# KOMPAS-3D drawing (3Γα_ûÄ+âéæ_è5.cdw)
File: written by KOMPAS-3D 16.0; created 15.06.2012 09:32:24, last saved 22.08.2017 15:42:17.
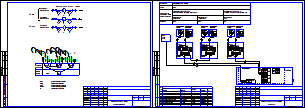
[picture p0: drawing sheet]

Sheets 1-2: A3, landscape

Title block, sheet 1: name: г. Москва, ул. Нежинская, д. 14, к.8 (кв. 1 и кв. 2); sheet number: 1; sheets: 27 / 28; sheet format: A3; stored path: D:\Проекты\Лыткарино\ул. Квартал 3А, д.25\710.74 РП.cdw; cell 320: Р
Title block, sheet 2: sheet number: 2

Views: Вид 2, Вид 3, Вид 4, Вид 5
Referenced files in C:\Program Files (x86)\ASCON\KOMPAS-3D V16\Sys\: SPDS.lcs, EngSys.lcs, GRAPHIC.LHS
Referenced files: graphic.tdp
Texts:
  МО, Клинский район, д. Решетниково, ул. Центральная, д.14
  GOST Common
  Normal
  List Paragraph
  heading 3
  для схемы
  txt
  краны
  Фоновая заливка
  Т0-элементы
  ВРУ
  Плата подключений
  СБ МКТС
  каб.
  Начало
  трассы
  Трассы
  Марка
  Проложен
  Датчик температуры (Т1)
  Датчик температуры (Т2)
  Датчик температуры (Т3)
  Датчик давления (Т1)
  Датчик давления (Т3)
  Датчик давления (Т2)
  Изм. модуль (Т1)
  Изм. модуль (Т2)
  ВРУ 220В, 50 Гц
  Изм. модуль (Т3)
  ИМ1 УУТЭ
  ИМ2 УУТЭ
  ИМ1 УУГВС
  ИМ2 УУГВС
  ИМ (Т1)
  FTP
  ПВС
  Конец
  Кол-во и
  сеч. жил
  Длина,
  Преобразователь расхода
  Термопреобразователь
  Преобразователь давления
  Преобразователь цифровой
  Системный блок МКТС
  приборы
  по месту
  шкаф
  учета
  UQIES
  Подающий
  трубопровод
  Обратный
  УУГВС
  УУТЭ
  Функциональная схема
  Агрегат
  Системный блок  МКТС
  Среда
  Вода
  параметра и место
  отбора импульса
  Учет тепловой энергии и
  теплоносителя системы отопления
  отопления
  расхода горячей воды системы ГВС
  ГВС
  ИМ1
  ИМ2
  ИМ3
  Pt 100
  Преобразователь
  температуры
  давления
  UP+
  UP-
  ИМП
  Лин
  Измерительный
  модуль М121
  Размеры, параметризация
  сит. план
  подача ГВС
  обратка ГВС
  хвс
  обратка
  POLYLINE_STYLE_0.25_RGB_0_0_0
  стены
  Основная (не является границей для штриховки)
  POLYLINE_STYLE_0.18_RGB_0_0_0
  ХВС
  зеленая
  Красная тонкая
  арматура
  Подача
  Скрытая линия
  Ось Z
  Ось Y
  Ось X
  Образующая трубопровода (проектируемого)
  Трубопровод толщиной 0.6мм (одна линия)
  Трубопровод толщиной 1.2мм (одна линия)
  Трубопровод толщиной 1.0мм (одна линия)
  Трубопровод толщиной 0.8мм (одна линия)
  Трубопровод существующий (одна линия)
  Трубопровод невидимый (одна линия)
  Трубопровод демонтируемый (одна линия)
  Осевая трубопровода
  Осевая трубопровода (демонтируемого)
  Образующая трубопровода (существующего)
  Образующая трубопровода (невидимого)
  Изолированный трубопровод проектируемый (одна линия)
  Изолированный трубопровод существующий (одна линия)
  Образующая изоляции
  Изоляция
  Изолированный трубопровод невидимый (одна линия)
  Штрих пвс 075
  штрих пвс 2,5
  существующее оборудование
  Существующее оборудование
  K5LT_BASIC_RGB_0_0_255_THICK_0.53
  POLYLINE_STYLE_1.51_RGB_0_0_255
  POLYLINE_STYLE_0.50_RGB_128_128_128
  K5LT_AXLED_RGB_255_128_0_SC_1_THICK_0.18
  ACAD_ISO04W100_RGB_0_0_0_SC_1_THICK_0.18
  тонкая черная
  пломбировка
  Провода
  синий штрих
  Стили документа
  G2co
  расход вторичной воды объемный
  расход вторичной воды объемный при 70гр
  Gco
  расход теплоносителя массовый
  расход теплоносит объемн подающ
  расход теплоносит объемн обр
  Лапир
  Ghvs
  Im1
  Im2
  Im3
  Im4
  Im5
  Khvs
  норматив ХВС
  число подъездов
  число этажей
  Nkv
  число квартир
  тепловая нагрузка на отопление
  сумма Q
  Qgvs
  тепловая нагрузка ГВС
  тепловая нагрузка на циркуляцию ГВС
  иммитовставка или под манометр
  ro1
  ro2
  ro3
  ro4
  верх предел темп граф
  нижн предел темп граф
  темп подачи ГВС
  темп обр ГВС
  темр хол воды
  vzdh
  Kchn
  Ktp
  Knp
  beta
  tnv
  Vклап
  KLP
  RPD
  RDS
  PUMP
  ro5
  Переход К-76 x 3-38 x 2-09Г2С ГОСТ 17378-2001
  Переход ГОСТ 17378-2001
  Переход
  ГОСТ
  Сталь 09Г2С ГОСТ 19281-89
  Переход К-76 x 3-45 x 2,5-09Г2С ГОСТ 17378-2001
  Переход К-57 x 3-38 x 2-09Г2С ГОСТ 17378-2001
  Переход К-57 x 3-32 x 2-09Г2С ГОСТ 17378-2001
  Втулка 20x50
  Переход К-108 x 4-57 x 3-09Г2С ГОСТ 17378-2001
  Переход К-45 x 2,5-32 x 2-09Г2С ГОСТ 17378-2001
  Переход К-89 x 3,5-45 x 2,5-09Г2С ГОСТ 17378-2001
  Переход К-133 x 5-108 x 4-09Г2С ГОСТ 17378-2001
  Переход К-159 x 4,5-89 x 3,5-09Г2С ГОСТ 17378-2001
  Переход К-45 x 2,5-38 x 2-09Г2С ГОСТ 17378-2001
  Фланец 1-32-1 Ст3сп ГОСТ 12820-80
  Фланцы
  Фланец
  квадратный
  Ст3сп
  Ст3сп ГОСТ 380-2005
  Переход К-57 x 3-45 x 2,5-09Г2С ГОСТ 17378-2001
  Переход К-76 x 3-57 x 3-09Г2С ГОСТ 17378-2001
  Фланец 1-50-16 Ст3сп ГОСТ 12821-80
  Переход К-89 x 3,5-76 x 3,5-09Г2С ГОСТ 17378-2001
  Переход К-108 x 4-89 x 3,5-09Г2С ГОСТ 17378-2001
  Тройник 159 x 4,5-09Г2С ГОСТ 17376-2001
  Тройники ГОСТ 17376-2001
  Тройник
  Отвод 90-159 x 4-09Г2С ГОСТ 17375-2001
  Отвод ГОСТ 17375-2001
  Отвод
  Переход К-108 x 4-76 x 3,5-09Г2С ГОСТ 17378-2001
  Переход К-159 x 4,5-108 x 4-09Г2С ГОСТ 17378-2001
  Переход К-133 x 5-76 x 3,5-09Г2С ГОСТ 17378-2001
  Переход К-133 x 4-89 x 3,5-09Г2С ГОСТ 17378-2001
  Переход К-1-42,4 x 2,6-21,3 x 2-TS10 ГОСТ 17378-2001
  TS10
  Сталь TS10 ИСО 2604/2-75
  Фланец 1-20-16 Ст3сп ГОСТ 12820-80
  Лит-Масса-Масштаб
  Материал-Предприятие
  Title Specification
  Body Specification ( left align )
  Body Specificaton ( centered )
  Поз.
  Кол.
  Приме-
  чание
  Таблица спецификации
  Засыпка
  Штрих3
  Штрих2
  Штрих1
  Песок
  Штр0.5пр7
  Штр0.5пр12
  Штр0.3пр10
  Штр1.4пр21.21
  Штр1пр15
  Штр2.12пр35
  Штр1.5пр25
  Штр2.82пр42.42
  Штр2пр30
  SACNCR_ISO 1
  Электрощитовая
  Пр-1
  Ок-1
  вапвыапвы
  Обозначение стандарта
  Типоразмер
  Разраб.
  Пров.
  Т.контр.
  Н.контр.
  Утв.
  автоматизации
  Рабочие чертежи основного комплекта. ГОСТ Р 21.1101-2009 Ф3
  Стадия
  Лист
  Листов
  Изм.
  Кол.уч.
  №док.
  Подп.
  Дата
  Изменение
  Номер документа
  Подпись
  Наименование объекта строительства, в состав которого входит здание, наим. микр
  Наименование здания (сооружения)
  Порядковый номер листа
  Количество листов в документе
  Наименование изображения
  Индекс предприятия, выпускающего документ
  Инв. № подл.
  Подп. и дата
  Взам. инв. №
  Инвентарный номер подлинника
  Подпись принявшего подлинник на хранение
  Инвентарный номер подлинника, взамен которого выпущен данный подлинник
  Согласовано
  Формат листа
  Согласование
  03 Рабочие чертежи основного комплекта. ГОСТ Р 21.1101-2009 Ф3
  Схема соединений внешних
  проводок
Dimensions and other numbers on the sheet: 0; 220В; 50Гц; 1; 2; 3; 6; 5; 4; 2x2x0,52; 3х0,75; 15; 25; 13; 1,2,3; 4,5,6; 7,8,9; 10,11,12; 8; 10; 11; 7; 12; 60; 4,0; 2,6582; 0,0160; 16; 95; 2,6160; 3,0; 0,7862; 0,0060; 70; 9; 4-20; 09Г2С; 17; 19; 20; 21; 22; 23; 24; 26; 30; 31; 33; 34; 52; 64; 65; 66; 67; 69; 71; 72; 73; 74; 75; 27; 28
